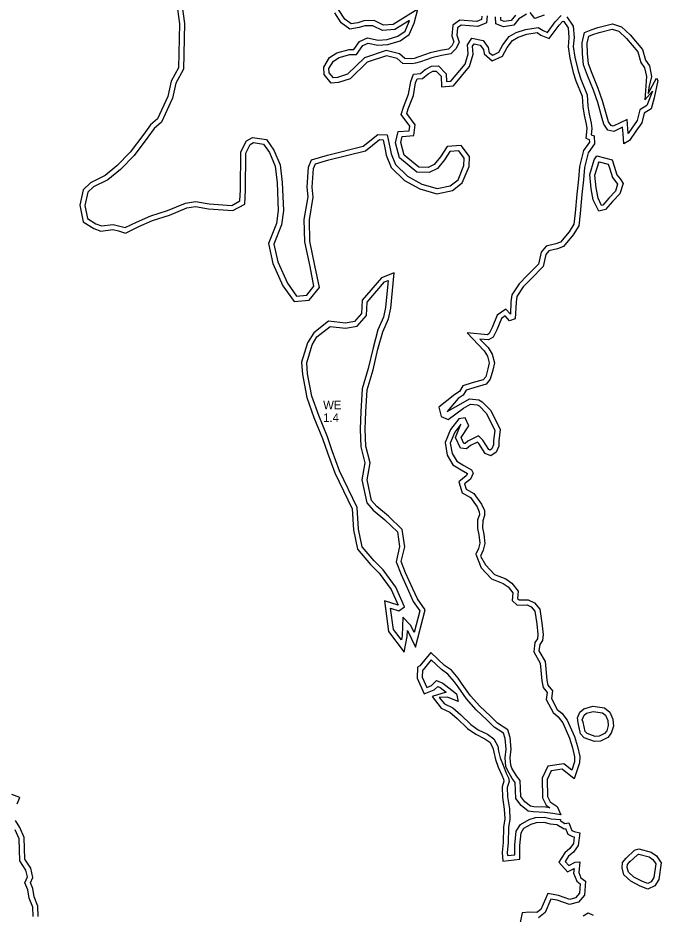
# Model space of a CAD drawing. Extents: x 2160437 to 2172832, y 205694 to 212444.
# Drawn here: x 2164674 to 2165055, y 208877 to 209408 of the extents above; entities that cross this region are included whole.
import ezdxf

# ---------------------------------------------------------------- set-up
doc = ezdxf.new("R2010")
doc.units = 0
for name, color, linetype in [('RD_EX_H2O', 7, 'Continuous'), ('RD_EX_H2O_Pond', 7, 'Continuous'), ('RD_EX_H2O_txCode', 7, 'Continuous'), ('RD_EX_VEG_ShrubLine', 7, 'Continuous')]:
    doc.layers.add(name, color=color, linetype=linetype)

msp = doc.modelspace()

# ---------------------------------------------------------------- linework, layer by layer
at = {"layer": 'RD_EX_H2O'}
for points in [[(2164769.41, 209426.43), (2164772.31, 209404.71), (2164771.69, 209377.65), (2164767.24, 209369.5), (2164765.25, 209360.55), (2164758.67, 209346.39), (2164754.38, 209342.66), (2164750.64, 209337.48), (2164742.41, 209326.63), (2164734.31, 209318.23), (2164726.87, 209312.12), (2164718.43, 209307.95), (2164715.04, 209304.78), (2164713.29, 209297.04), (2164714.91, 209289.2), (2164719.88, 209286.09), (2164723.08, 209284.91), (2164729.98, 209285.75), (2164734.05, 209284.78), (2164737.11, 209283.85), (2164743.97, 209287.16), (2164752.33, 209290.88), (2164762.32, 209294.06), (2164772.81, 209298.4), (2164778.77, 209299.41), (2164786.86, 209298.05), (2164800.32, 209297.05), (2164805.08, 209299.67), (2164805.44, 209306.17), (2164805.67, 209328.72), (2164808.98, 209335.23), (2164812.61, 209337.33), (2164820.89, 209336), (2164825.27, 209329.8), (2164828.91, 209321.11), (2164830.18, 209310.6), (2164830.88, 209293.93), (2164829.82, 209285.59), (2164825.27, 209274.12), (2164827.57, 209263.63), (2164833.26, 209250.92), (2164838.65, 209243.19), (2164844.68, 209243.81), (2164848.97, 209249.16), (2164846.64, 209260.81), (2164843.58, 209275.53), (2164843.26, 209288.74), (2164845.47, 209302.08), (2164845, 209307.8), (2164845.71, 209319.66), (2164847.61, 209324.09), (2164856.98, 209326.85), (2164878.13, 209332.09), (2164886.91, 209339.05), (2164892.41, 209338.77), (2164894.19, 209330.61), (2164894.63, 209327.54), (2164897.2, 209321.18), (2164904.32, 209314.25), (2164912.89, 209309.67), (2164921.97, 209307.02), (2164929.74, 209308.61), (2164934.39, 209312.18), (2164937.85, 209320.66), (2164938.04, 209325.01), (2164934.75, 209329.34), (2164929.54, 209328.96), (2164926.36, 209323.95), (2164922.11, 209318.82), (2164917.19, 209316.51), (2164909.94, 209316.79), (2164899.72, 209325.1), (2164897.31, 209334.14), (2164898.85, 209340.71), (2164905.45, 209341.26), (2164905.83, 209344.02), (2164900.71, 209350.85), (2164902, 209355.25), (2164904.96, 209362.99), (2164906.3, 209370.49), (2164907.89, 209374.75), (2164912.14, 209375.15), (2164914.84, 209377.43), (2164918.66, 209379.57), (2164922.68, 209379.58), (2164927.31, 209374.89), (2164927.42, 209370.41), (2164930.04, 209370.63), (2164938.45, 209380.68), (2164940.23, 209386.85), (2164939.86, 209392.1), (2164942.5, 209396.03), (2164949.28, 209394.7), (2164952.22, 209390.52), (2164952.81, 209387.38), (2164954.86, 209386.05), (2164958.48, 209387.74), (2164960.93, 209392.17), (2164964.63, 209397), (2164968.71, 209399.45), (2164974.37, 209401.26), (2164981.79, 209402.46), (2164984.7, 209400.51), (2164987.3, 209399.48), (2164991.94, 209405.75), (2164995.47, 209409.52)], [(2164951.48, 209409.23), (2164951.1, 209405.14), (2164946.08, 209402.87), (2164936.18, 209403.66), (2164934, 209402.11), (2164933.61, 209397.85), (2164935, 209393.7), (2164933.24, 209389.86), (2164930.14, 209386.8), (2164924.48, 209385.78), (2164918.75, 209384.48), (2164912.11, 209382.09), (2164909.14, 209381.19), (2164906.97, 209380.77), (2164901.54, 209381.08), (2164898.19, 209384.07), (2164891.96, 209385.57), (2164880.58, 209381.81), (2164870.44, 209372.04), (2164863.57, 209369.81), (2164859.18, 209369.36), (2164855.02, 209374.44), (2164854.86, 209378.95), (2164858.23, 209384.53), (2164862.59, 209387.45), (2164869.75, 209389.43), (2164872.63, 209389.41), (2164875.99, 209394.03), (2164880.7, 209396.26), (2164887.01, 209394.96), (2164892.27, 209395.32), (2164898.66, 209397.17), (2164902.94, 209400.18), (2164905.42, 209405.92), (2164905.61, 209406.61), (2164896.88, 209401.25), (2164889.67, 209400.67), (2164883.95, 209403.45), (2164879.07, 209403.4), (2164875.71, 209402.31), (2164870.26, 209401.37), (2164865.08, 209405.1), (2164861.28, 209410.99)], [(2164998.85, 209408.62), (2165002.52, 209403.1), (2165003.04, 209396.45), (2165002.58, 209391.08), (2165003.41, 209384.84), (2165005.46, 209376.62), (2165007.01, 209371.74), (2165010.78, 209362.4), (2165011.23, 209355.72), (2165012.01, 209351.12), (2165013.19, 209345.68), (2165013.61, 209342.56), (2165013.24, 209338.89), (2165014.98, 209338.23), (2165015.13, 209333.55), (2165011.45, 209328.23), (2165009.25, 209319.5), (2165008.56, 209312.25), (2165007.64, 209303.43), (2165006.71, 209292.27), (2165005.88, 209284.85), (2165002.57, 209279.55), (2164996.8, 209272.76), (2164993.23, 209271.34), (2164988.19, 209270.1), (2164986.3, 209268), (2164984.77, 209260.77), (2164977.46, 209253.34), (2164972.84, 209248.74), (2164969.11, 209243.02), (2164968.67, 209239.74), (2164968.22, 209229.93), (2164964.74, 209228.72), (2164962.18, 209231.59), (2164960.04, 209230.02), (2164957.36, 209223.42), (2164955.09, 209218.97), (2164952.46, 209217.38), (2164947.29, 209217.88), (2164948.42, 209216.65), (2164952.13, 209212.85), (2164954.55, 209208.84), (2164955.89, 209203.75), (2164954.91, 209199.51), (2164953.44, 209194.17), (2164951, 209191.11), (2164943.6, 209189.01), (2164939.12, 209187.7), (2164937.32, 209184.59), (2164934.39, 209182.72), (2164927.81, 209175.03), (2164936.04, 209179.53), (2164941.1, 209182.44), (2164946.55, 209181.88), (2164948.66, 209180.71), (2164953.71, 209175.59), (2164959.19, 209164.29), (2164958.42, 209157.56), (2164958.39, 209154.52), (2164956.81, 209150.96), (2164953.7, 209148.68), (2164950.45, 209150.13), (2164946.62, 209156.08), (2164945.84, 209156.9), (2164941.74, 209154.82), (2164939.34, 209152.78), (2164935.7, 209153.37), (2164932.89, 209159.59), (2164935.98, 209167.39), (2164932.47, 209162.83), (2164929.73, 209156.26), (2164930.75, 209150.17), (2164933.51, 209145.59), (2164937.67, 209143.08), (2164942.38, 209140.46), (2164943.36, 209138.47), (2164941.61, 209134.93), (2164938.18, 209132.19), (2164939.19, 209128.93), (2164943.7, 209126.39), (2164948.19, 209120.02), (2164949.9, 209116.32), (2164950.04, 209113.39), (2164948.91, 209110.29), (2164948.83, 209106.07), (2164949.61, 209102.43), (2164950.17, 209096.79), (2164949.24, 209092.94), (2164947.62, 209089.29), (2164950.53, 209084.22), (2164955.85, 209078.38), (2164962.57, 209075.82), (2164966.12, 209073.29), (2164969.97, 209068.59), (2164969.45, 209064.32), (2164970.48, 209063.39), (2164975.85, 209063.46), (2164979.58, 209061.75), (2164982.68, 209057.92), (2164983.89, 209049.71), (2164984.65, 209042.9), (2164984.37, 209039.3), (2164982.69, 209037), (2164982.27, 209033.34), (2164985.9, 209026.94), (2164986.93, 209015.88), (2164987.56, 209012.84), (2164990.22, 209009.5), (2164989.66, 209005.01), (2164993.12, 208998.62), (2164995.76, 208996.32), (2164998.89, 208992.17), (2165003.21, 208982.58), (2165005.06, 208976.61), (2165006.39, 208970.69), (2165006.26, 208967.03), (2165003.15, 208957.44), (2164996.09, 208963.15), (2164989.56, 208962.21), (2164987.14, 208957.16), (2164987.3, 208946.97), (2164988.79, 208943.85), (2164993.06, 208941.05), (2164995.28, 208936.18)], [(2164974.83, 209410.26), (2164970.35, 209407.45), (2164967.38, 209403.73), (2164961.32, 209402.76), (2164956.77, 209404.54), (2164956.58, 209408.7)], [(2164985.38, 209409.71), (2164979.78, 209407.76), (2164976.97, 209411.17)], [(2164995.28, 208936.18), (2164990.55, 208937.01), (2164985.79, 208937.63), (2164978.91, 208937.92), (2164975.94, 208938.4), (2164971.77, 208941.69), (2164968.48, 208945.9), (2164968.19, 208955.38), (2164966.47, 208957.58), (2164963.52, 208962.55), (2164962.67, 208964.84), (2164962.22, 208969.89), (2164962.75, 208975), (2164962.31, 208981.3), (2164961.3, 208984.57), (2164955.74, 208988.11), (2164951.39, 208992.5), (2164945.11, 208998.34), (2164939.39, 209004.77), (2164934.4, 209011.9), (2164932.09, 209015.2), (2164928.36, 209019.5), (2164924.45, 209022.19), (2164918.45, 209027.84), (2164913.59, 209022.03), (2164913.19, 209021.79), (2164913.06, 209017.71), (2164915.85, 209011.56), (2164918.54, 209012.64), (2164921.61, 209015.77), (2164925.27, 209014.15), (2164930.57, 209009.88), (2164933.38, 209007.86), (2164934.31, 209003.19), (2164928.01, 209005.74), (2164923.21, 209005.59), (2164926.21, 209001.81), (2164931.2, 208999.42), (2164935.92, 208995.34), (2164941.81, 208989.55), (2164946.34, 208986.53), (2164951.74, 208983.83), (2164955.52, 208981.14), (2164957.88, 208976.86), (2164958.38, 208973.94), (2164959.31, 208969.81), (2164960.95, 208965.54), (2164962.91, 208960.9), (2164964.24, 208958.09), (2164964.51, 208955.87), (2164963.43, 208952.34), (2164963.71, 208946.76), (2164964.72, 208939.72), (2164965.03, 208933.65), (2164964.16, 208928.58), (2164963.99, 208919.54), (2164963.46, 208913.9), (2164963.62, 208912.09), (2164967.89, 208912.54), (2164967.9, 208918.23), (2164968.74, 208926.48), (2164971.23, 208930.48), (2164976.49, 208933.42), (2164980.16, 208934.67), (2164985.45, 208934.84), (2164989.4, 208933.87), (2164994.92, 208933.32)], [(2164994.92, 208933.32), (2164994.85, 208932.77), (2164997.65, 208931.11), (2164999.86, 208931.51), (2165001.79, 208926.94), (2165003.1, 208926.24), (2165006.51, 208925.56), (2165005.51, 208918.03), (2165002.68, 208914.07), (2164999.84, 208911.74), (2164997.81, 208908.5), (2164999.91, 208906.07), (2165003.74, 208908.09), (2165006.52, 208908.41), (2165005.81, 208901.95), (2165007.06, 208898.82), (2165009.83, 208896.82), (2165009.2, 208888.65), (2165005.57, 208884.38), (2165000.39, 208882.96), (2164993.08, 208885.54), (2164989.37, 208886.23), (2164985.84, 208878.27), (2164981.98, 208875.24)], [(2164682.67, 208875.91), (2164682.51, 208881.38), (2164680.25, 208886.82), (2164679.58, 208891.79), (2164677.77, 208895.95), (2164679.25, 208899.43), (2164678.4, 208903.46), (2164674.69, 208908.88), (2164674.4, 208922.01), (2164672.02, 208927.32)], [(2165008.52, 208876.42), (2165011.46, 208878.05), (2165014.32, 208876.67)]]:
    msp.add_lwpolyline(points, dxfattribs=at)
for points in [[(2165019.73, 209348.39), (2165017.1, 209358), (2165014.46, 209365.17), (2165010.94, 209373.98), (2165008.71, 209380.18), (2165007.99, 209386.79), (2165007.83, 209393.34), (2165009.13, 209399.36), (2165013.2, 209400.97), (2165017.08, 209402.3), (2165025.78, 209404.62), (2165031.04, 209402.82), (2165036.25, 209397.94), (2165043.48, 209389.39), (2165045.35, 209382.93), (2165047.66, 209379.75), (2165048.96, 209373.36), (2165047.3, 209366.78), (2165046.85, 209363.33), (2165051.83, 209372.39), (2165052.61, 209370.9), (2165050.51, 209360.63), (2165048.64, 209354.26), (2165044.64, 209351.72), (2165043.17, 209345.96), (2165039.71, 209341.02), (2165035.88, 209335.47), (2165032.44, 209333.4), (2165032.04, 209339.39), (2165031.79, 209343.28), (2165026.5, 209340.83), (2165023.13, 209341.6), (2165020.69, 209345.14)], [(2165015, 209323.93), (2165016.58, 209326.29), (2165025.59, 209323.91), (2165026.84, 209320.24), (2165028.43, 209315.04), (2165030.26, 209312.67), (2165032.05, 209310.08), (2165030.17, 209303.96), (2165025.87, 209299.27), (2165021.61, 209294.51), (2165017.7, 209293.54), (2165014.35, 209300.3), (2165013.21, 209306.92), (2165012.3, 209315.3)], [(2165005.09, 208993.52), (2165006.55, 208996.95), (2165008.89, 208998.97), (2165014.16, 209000.47), (2165021.08, 208999.44), (2165024.14, 208997), (2165026, 208992.82), (2165026.36, 208988.65), (2165025.1, 208984.59), (2165023.09, 208981.95), (2165018.63, 208979.85), (2165015.11, 208979.49), (2165009, 208981.66), (2165006.8, 208984.14), (2165005.45, 208990.55)], [(2165033.94, 208910.52), (2165038.93, 208915.14), (2165041.34, 208916.11), (2165048.67, 208914), (2165051.96, 208911.94), (2165054.58, 208907.72), (2165053.24, 208897.94), (2165050.85, 208894.03), (2165046.74, 208892.2), (2165042.29, 208893.93), (2165036.69, 208896.83), (2165032.47, 208900.56), (2165031.54, 208904.81), (2165031.81, 208907.87)]]:
    msp.add_lwpolyline(points, close=True, dxfattribs=at)
at = {"layer": 'RD_EX_H2O_Pond'}
msp.add_lwpolyline([(2164850.7, 209219.27), (2164858.56, 209225.37), (2164867.68, 209224.32), (2164874.55, 209225.48), (2164880.14, 209231.87), (2164880.51, 209239.73), (2164890.85, 209251.69), (2164893.02, 209252.53), (2164891.45, 209236.56), (2164890.2, 209230.76), (2164886.87, 209223.25), (2164883.97, 209212.67), (2164881.15, 209200.37), (2164877.54, 209188.43), (2164876.74, 209175), (2164876.39, 209164.48), (2164876.67, 209154.05), (2164879.17, 209144.55), (2164877.34, 209134.45), (2164880.32, 209120.9), (2164884.05, 209116.61), (2164891.04, 209110.75), (2164898.48, 209103.74), (2164899.67, 209095.06), (2164897.58, 209086.04), (2164900.54, 209078.37), (2164904.91, 209068.76), (2164907.79, 209062.57), (2164911.68, 209057.01), (2164908.35, 209044.1), (2164906.35, 209048.23), (2164901.7, 209053.16), (2164901.28, 209042.2), (2164900.76, 209039.68), (2164896, 209045.98), (2164894.39, 209058.56), (2164899.32, 209056.98), (2164902.54, 209059.38), (2164897.39, 209071.02), (2164889.95, 209081.27), (2164884.61, 209086.52), (2164877.5, 209094.82), (2164875.45, 209105.32), (2164874.56, 209118.19), (2164864.18, 209139.93), (2164859.77, 209151.6), (2164856.92, 209160.05), (2164851.78, 209172.52), (2164847.71, 209184.15), (2164845.19, 209197.38), (2164844.69, 209203.83), (2164847.98, 209214.48)], close=True, dxfattribs=at)
at = {"layer": 'RD_EX_VEG_ShrubLine'}
for points in [[(2164766.37, 209426.53), (2164769.3, 209404.55), (2164768.71, 209378.45), (2164764.4, 209370.56), (2164762.39, 209361.52), (2164756.22, 209348.23), (2164752.15, 209344.69), (2164748.23, 209339.26), (2164740.13, 209328.58), (2164732.28, 209320.44), (2164725.23, 209314.66), (2164716.7, 209310.45), (2164712.32, 209306.34), (2164710.22, 209297.07), (2164712.23, 209287.33), (2164718.56, 209283.38), (2164722.72, 209281.85), (2164729.81, 209282.71), (2164733.26, 209281.89), (2164737.35, 209280.64), (2164745.23, 209284.44), (2164753.4, 209288.07), (2164763.35, 209291.25), (2164773.64, 209295.5), (2164778.77, 209296.37), (2164786.5, 209295.06), (2164800.99, 209293.99), (2164807.98, 209297.85), (2164808.44, 209306.07), (2164808.67, 209327.99), (2164811.25, 209333.07), (2164813.19, 209334.2), (2164819.17, 209333.24), (2164822.63, 209328.33), (2164825.98, 209320.34), (2164827.19, 209310.35), (2164827.87, 209294.05), (2164826.89, 209286.34), (2164822.15, 209274.37), (2164824.71, 209262.68), (2164830.64, 209249.43), (2164837.2, 209240.03), (2164846.24, 209240.96), (2164852.19, 209248.38), (2164849.58, 209261.41), (2164846.57, 209275.87), (2164846.27, 209288.52), (2164848.49, 209301.96), (2164848.01, 209307.83), (2164848.67, 209318.95), (2164849.81, 209321.61), (2164857.77, 209323.95), (2164879.48, 209329.34), (2164887.88, 209336), (2164889.97, 209335.89), (2164891.23, 209330.07), (2164891.71, 209326.75), (2164894.66, 209319.47), (2164902.53, 209311.8), (2164911.75, 209306.87), (2164921.84, 209303.93), (2164931.02, 209305.8), (2164936.86, 209310.3), (2164940.82, 209320), (2164941.08, 209325.96), (2164936.15, 209332.46), (2164927.81, 209331.83), (2164923.93, 209325.72), (2164920.23, 209321.25), (2164916.57, 209319.54), (2164911.05, 209319.75), (2164902.37, 209326.81), (2164900.41, 209334.18), (2164901.27, 209337.9), (2164908.09, 209338.47), (2164908.98, 209344.83), (2164904.01, 209351.45), (2164904.85, 209354.29), (2164907.86, 209362.19), (2164909.21, 209369.69), (2164910.05, 209371.94), (2164913.36, 209372.25), (2164916.55, 209374.96), (2164919.45, 209376.57), (2164921.43, 209376.58), (2164924.35, 209373.63), (2164924.5, 209367.15), (2164931.54, 209367.74), (2164941.16, 209379.24), (2164943.26, 209386.53), (2164942.93, 209391.28), (2164943.88, 209392.7), (2164947.52, 209391.99), (2164949.4, 209389.32), (2164949.86, 209386.83), (2164949.86, 209386.83), (2164954.62, 209382.63), (2164960.64, 209385.44), (2164963.45, 209390.53), (2164966.66, 209394.72), (2164969.96, 209396.7), (2164975.07, 209398.33), (2164981.11, 209399.31), (2164983.3, 209397.84), (2164988.34, 209395.83), (2164994.25, 209403.82), (2164996.44, 209406.16), (2164996.98, 209406.01), (2164999.59, 209402.09), (2165000.03, 209396.46), (2164999.56, 209391.01), (2165000.46, 209384.28), (2165002.57, 209375.8), (2165004.18, 209370.72), (2165007.81, 209361.72), (2165008.25, 209355.37), (2165009.06, 209350.55), (2165010.23, 209345.16), (2165010.59, 209342.51), (2165010.02, 209336.89), (2165012.05, 209336.13), (2165012.1, 209334.45), (2165008.67, 209329.49), (2165006.29, 209320.01), (2165005.57, 209312.55), (2165004.66, 209303.71), (2165003.73, 209292.57), (2165002.97, 209285.86), (2165000.14, 209281.32), (2164994.99, 209275.27), (2164992.32, 209274.21), (2164986.58, 209272.79), (2164983.53, 209269.41), (2164982.02, 209262.25), (2164975.33, 209255.46), (2164970.5, 209250.64), (2164966.22, 209244.09), (2164965.68, 209240.01), (2164965.33, 209232.56), (2164962.6, 209235.63), (2164957.58, 209231.93), (2164954.63, 209224.67), (2164952.8, 209221.09), (2164951.75, 209220.46), (2164939.72, 209221.62), (2164946.25, 209214.58), (2164949.74, 209211), (2164951.76, 209207.66), (2164952.8, 209203.71), (2164952, 209200.25), (2164950.71, 209195.56), (2164949.26, 209193.74), (2164942.76, 209191.89), (2164937.12, 209190.24), (2164935.09, 209186.73), (2164932.4, 209185.01), (2164922.95, 209177.53), (2164924.29, 209171.96), (2164928.51, 209170.25), (2164937.5, 209176.92), (2164941.76, 209179.36), (2164945.63, 209178.96), (2164946.83, 209178.29), (2164951.22, 209173.84), (2164956.11, 209163.77), (2164955.42, 209157.75), (2164955.39, 209155.17), (2164954.39, 209152.91), (2164953.33, 209152.13), (2164952.48, 209152.5), (2164948.99, 209157.94), (2164946.49, 209160.6), (2164940.07, 209157.34), (2164938.45, 209155.96), (2164937.77, 209156.07), (2164936.15, 209159.67), (2164940.76, 209166.48), (2164938.57, 209171.26), (2164934.71, 209170.64)], [(2164948.45, 209409.06), (2164948.27, 209407.15), (2164945.55, 209405.92), (2164935.34, 209406.74), (2164931.14, 209403.76), (2164930.56, 209397.5), (2164931.78, 209393.87), (2164930.74, 209391.61), (2164928.7, 209389.59), (2164923.88, 209388.72), (2164917.9, 209387.37), (2164911.17, 209384.94), (2164908.42, 209384.11), (2164906.77, 209383.79), (2164902.75, 209384.02), (2164899.62, 209386.81), (2164891.83, 209388.69), (2164878.99, 209384.44), (2164868.85, 209374.68), (2164862.95, 209372.76), (2164860.48, 209372.51), (2164857.98, 209375.56), (2164857.89, 209378.16), (2164860.46, 209382.41), (2164863.85, 209384.69), (2164870.15, 209386.42), (2164874.15, 209386.4), (2164877.97, 209391.65), (2164881.08, 209393.12), (2164886.81, 209391.94), (2164892.79, 209392.35), (2164899.98, 209394.42), (2164905.35, 209398.22), (2164908.25, 209404.92), (2164910.49, 209413.13), (2164895.92, 209404.19), (2164890.24, 209403.73), (2164884.62, 209406.46), (2164878.58, 209406.39), (2164874.99, 209405.23), (2164870.99, 209404.54), (2164867.29, 209407.21), (2164863.49, 209413.09)], [(2164968.32, 209409.72), (2164965.76, 209406.51), (2164961.65, 209405.85), (2164959.68, 209406.63), (2164959.59, 209408.48)], [(2165022.62, 209349.18), (2165019.96, 209358.92), (2165017.26, 209366.24), (2165013.74, 209375.04), (2165011.66, 209380.86), (2165010.98, 209386.99), (2165010.84, 209393.05), (2165011.72, 209397.16), (2165014.23, 209398.15), (2165017.96, 209399.43), (2165025.67, 209401.48), (2165029.46, 209400.19), (2165034.07, 209395.87), (2165040.78, 209387.94), (2165042.62, 209381.59), (2165044.85, 209378.52), (2165045.89, 209373.43), (2165044.93, 209359.5), (2165049.57, 209364.74), (2165046.08, 209356.19), (2165042.03, 209353.62), (2165040.39, 209347.23), (2165037.25, 209342.73), (2165035.04, 209339.53), (2165035.03, 209339.59), (2165034.49, 209347.84), (2165026.17, 209343.98), (2165024.94, 209344.26), (2165023.43, 209346.45), (2165022.6, 209349.24)], [(2165017.48, 209322.26), (2165017.88, 209322.84), (2165023.27, 209321.42), (2165023.99, 209319.31), (2165025.72, 209313.64), (2165027.83, 209310.9), (2165028.75, 209309.57), (2165027.5, 209305.48), (2165023.65, 209301.28), (2165019.99, 209297.2), (2165019.32, 209297.03), (2165017.23, 209301.25), (2165016.18, 209307.34), (2165015.35, 209315), (2165017.86, 209323.04)], [(2164934.71, 209170.64), (2164929.85, 209164.35), (2164926.63, 209156.61), (2164927.88, 209149.11), (2164931.33, 209143.4), (2164936.17, 209140.49), (2164939.96, 209138.37), (2164939.22, 209136.85), (2164934.71, 209133.26), (2164936.67, 209126.9), (2164941.63, 209124.11), (2164945.58, 209118.51), (2164946.93, 209115.6), (2164947.01, 209113.85), (2164945.91, 209110.85), (2164945.83, 209105.78), (2164946.64, 209101.97), (2164947.13, 209097), (2164946.39, 209093.91), (2164944.88, 209090.5), (2164944.88, 209090.5), (2164948.09, 209082.44), (2164954.12, 209075.83), (2164961.14, 209073.16), (2164964.05, 209071.08), (2164966.84, 209067.68), (2164966.29, 209063.15), (2164969.33, 209060.37), (2164975.21, 209060.46), (2164977.69, 209059.32), (2164979.83, 209056.67), (2164980.92, 209049.32), (2164981.64, 209042.85), (2164981.45, 209040.38), (2164979.8, 209038.12), (2164979.18, 209032.72), (2164982.97, 209026.02), (2164983.96, 209015.43), (2164984.77, 209011.53), (2164987.09, 209008.62), (2164986.57, 209004.43), (2164990.74, 208996.72), (2164993.55, 208994.26), (2164996.29, 208990.63), (2165000.4, 208981.52), (2165002.16, 208975.84), (2165003.38, 208970.4), (2165003.28, 208967.55), (2165001.64, 208962.51), (2164996.96, 208966.3), (2164987.55, 208964.95), (2164984.13, 208957.82), (2164984.31, 208946.26), (2164986.45, 208941.79), (2164988.64, 208940.36)], [(2164988.64, 208940.36), (2164986.05, 208940.62), (2164979.21, 208940.91), (2164977.19, 208941.24), (2164973.91, 208943.82), (2164971.45, 208946.97), (2164971.16, 208956.45), (2164968.95, 208959.28), (2164966.24, 208963.84), (2164965.63, 208965.5), (2164965.23, 208969.88), (2164965.76, 208974.95), (2164965.27, 208981.86), (2164963.84, 208986.51), (2164957.63, 208990.46), (2164953.48, 208994.66), (2164947.25, 209000.44), (2164941.75, 209006.64), (2164936.86, 209013.62), (2164934.46, 209017.05), (2164930.37, 209021.75), (2164926.35, 209024.52), (2164918.19, 209032.21), (2164911.62, 209024.34), (2164910.24, 209023.53), (2164910.04, 209017.11), (2164914.3, 209007.71), (2164920.24, 209010.09), (2164922.3, 209012.19), (2164923.69, 209011.57), (2164927.23, 209008.72), (2164919.07, 209006.13), (2164924.28, 208999.4), (2164929.54, 208996.88), (2164933.89, 208993.13), (2164939.91, 208987.22), (2164944.83, 208983.93), (2164950.19, 208981.25), (2164953.22, 208979.09), (2164955, 208975.85), (2164955.44, 208973.35), (2164956.43, 208968.94), (2164958.17, 208964.42), (2164960.17, 208959.67), (2164961.32, 208957.24), (2164961.46, 208956.14), (2164960.4, 208952.72), (2164960.72, 208946.47), (2164961.73, 208939.43), (2164962.01, 208933.83), (2164961.16, 208928.86), (2164960.99, 208919.71), (2164960.45, 208913.91), (2164960.9, 208908.79), (2164970.89, 208909.83), (2164970.9, 208918.07), (2164971.66, 208925.49), (2164973.37, 208928.23), (2164977.72, 208930.67), (2164980.71, 208931.68), (2164985.14, 208931.82), (2164988.89, 208930.9), (2164992.82, 208930.51)], [(2164673.27, 208942.73), (2164674.87, 208946.34), (2164670.05, 208948.22)], [(2164685.67, 208875.94), (2164685.5, 208882.02), (2164683.17, 208887.61), (2164682.5, 208892.6), (2164681.04, 208895.96), (2164682.38, 208899.12), (2164681.21, 208904.66), (2164677.67, 208909.84), (2164677.39, 208922.69), (2164674.69, 208928.71), (2164672.23, 208932.85)], [(2164992.82, 208930.51), (2164997.08, 208927.96), (2164998.03, 208928.13), (2164999.44, 208924.79), (2165002.08, 208923.38), (2165003.17, 208923.16), (2165002.64, 208919.17), (2165000.47, 208916.14), (2164997.56, 208913.74), (2164994.09, 208908.22), (2164999.2, 208902.31), (2165003.06, 208904.34), (2165002.75, 208901.54), (2165004.6, 208896.9), (2165006.71, 208895.37), (2165006.29, 208889.85), (2165003.89, 208887.03), (2165000.5, 208886.1), (2164993.86, 208888.45), (2164987.59, 208889.61), (2164983.4, 208880.17), (2164981, 208878.28), (2164976.54, 208878.47), (2164972.27, 208878.05), (2164970.26, 208868.74)], [(2165035.98, 208908.32), (2165040.56, 208912.56), (2165041.5, 208912.94), (2165047.44, 208911.23), (2165049.78, 208909.76), (2165051.46, 208907.05), (2165050.36, 208898.97), (2165048.77, 208896.39), (2165046.66, 208895.45), (2165043.53, 208896.67), (2165038.4, 208899.33), (2165035.19, 208902.16), (2165034.56, 208905), (2165034.72, 208906.69), (2165036.28, 208908.64)]]:
    msp.add_lwpolyline(points, dxfattribs=at)
for points in [[(2164848.86, 209221.64), (2164845.21, 209215.68), (2164841.66, 209204.17), (2164842.21, 209196.98), (2164844.81, 209183.37), (2164848.98, 209171.45), (2164854.11, 209159), (2164856.94, 209150.59), (2164861.42, 209138.75), (2164871.6, 209117.41), (2164872.47, 209104.93), (2164874.71, 209093.47), (2164882.41, 209084.47), (2164887.67, 209079.3), (2164894.78, 209069.51), (2164898.83, 209060.36), (2164898.77, 209060.31), (2164890.81, 209062.87), (2164893.13, 209044.81), (2164902.36, 209032.57), (2164904.27, 209041.84), (2164904.4, 209045.36), (2164909.22, 209035.45), (2164914.93, 209057.6), (2164910.4, 209064.07), (2164907.63, 209070.02), (2164903.3, 209079.53), (2164900.71, 209086.26), (2164902.71, 209094.92), (2164901.31, 209105.2), (2164893.04, 209113), (2164886.16, 209118.76), (2164883.08, 209122.29), (2164880.4, 209134.51), (2164882.25, 209144.67), (2164879.66, 209154.48), (2164879.39, 209164.48), (2164879.73, 209174.86), (2164880.51, 209187.9), (2164884.06, 209199.6), (2164886.88, 209211.94), (2164889.7, 209222.24), (2164893.06, 209229.83), (2164894.42, 209236.1), (2164896.48, 209257.08), (2164889.07, 209254.22), (2164877.56, 209240.91), (2164877.19, 209233.05), (2164872.99, 209228.26), (2164867.61, 209227.35), (2164857.69, 209228.49)], [(2165007.85, 208992.35), (2165009.04, 208995.14), (2165010.35, 208996.27), (2165014.36, 208997.41), (2165019.84, 208996.59), (2165021.69, 208995.11), (2165023.05, 208992.06), (2165023.32, 208988.97), (2165022.4, 208985.98), (2165021.15, 208984.35), (2165017.81, 208982.78), (2165015.48, 208982.54), (2165010.73, 208984.23), (2165009.57, 208985.53), (2165008.41, 208991.04)]]:
    msp.add_lwpolyline(points, close=True, dxfattribs=at)

# ---------------------------------------------------------------- texts
at = {"layer": 'RD_EX_H2O_txCode'}
for s, p in [('WE', (2164854.45, 209176.31)), ('1.4', (2164854.45, 209168.81))]:
    msp.add_text(s, height=5, dxfattribs=at).set_placement(p)

doc.saveas('drawing.dxf')
